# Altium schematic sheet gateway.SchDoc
size A3
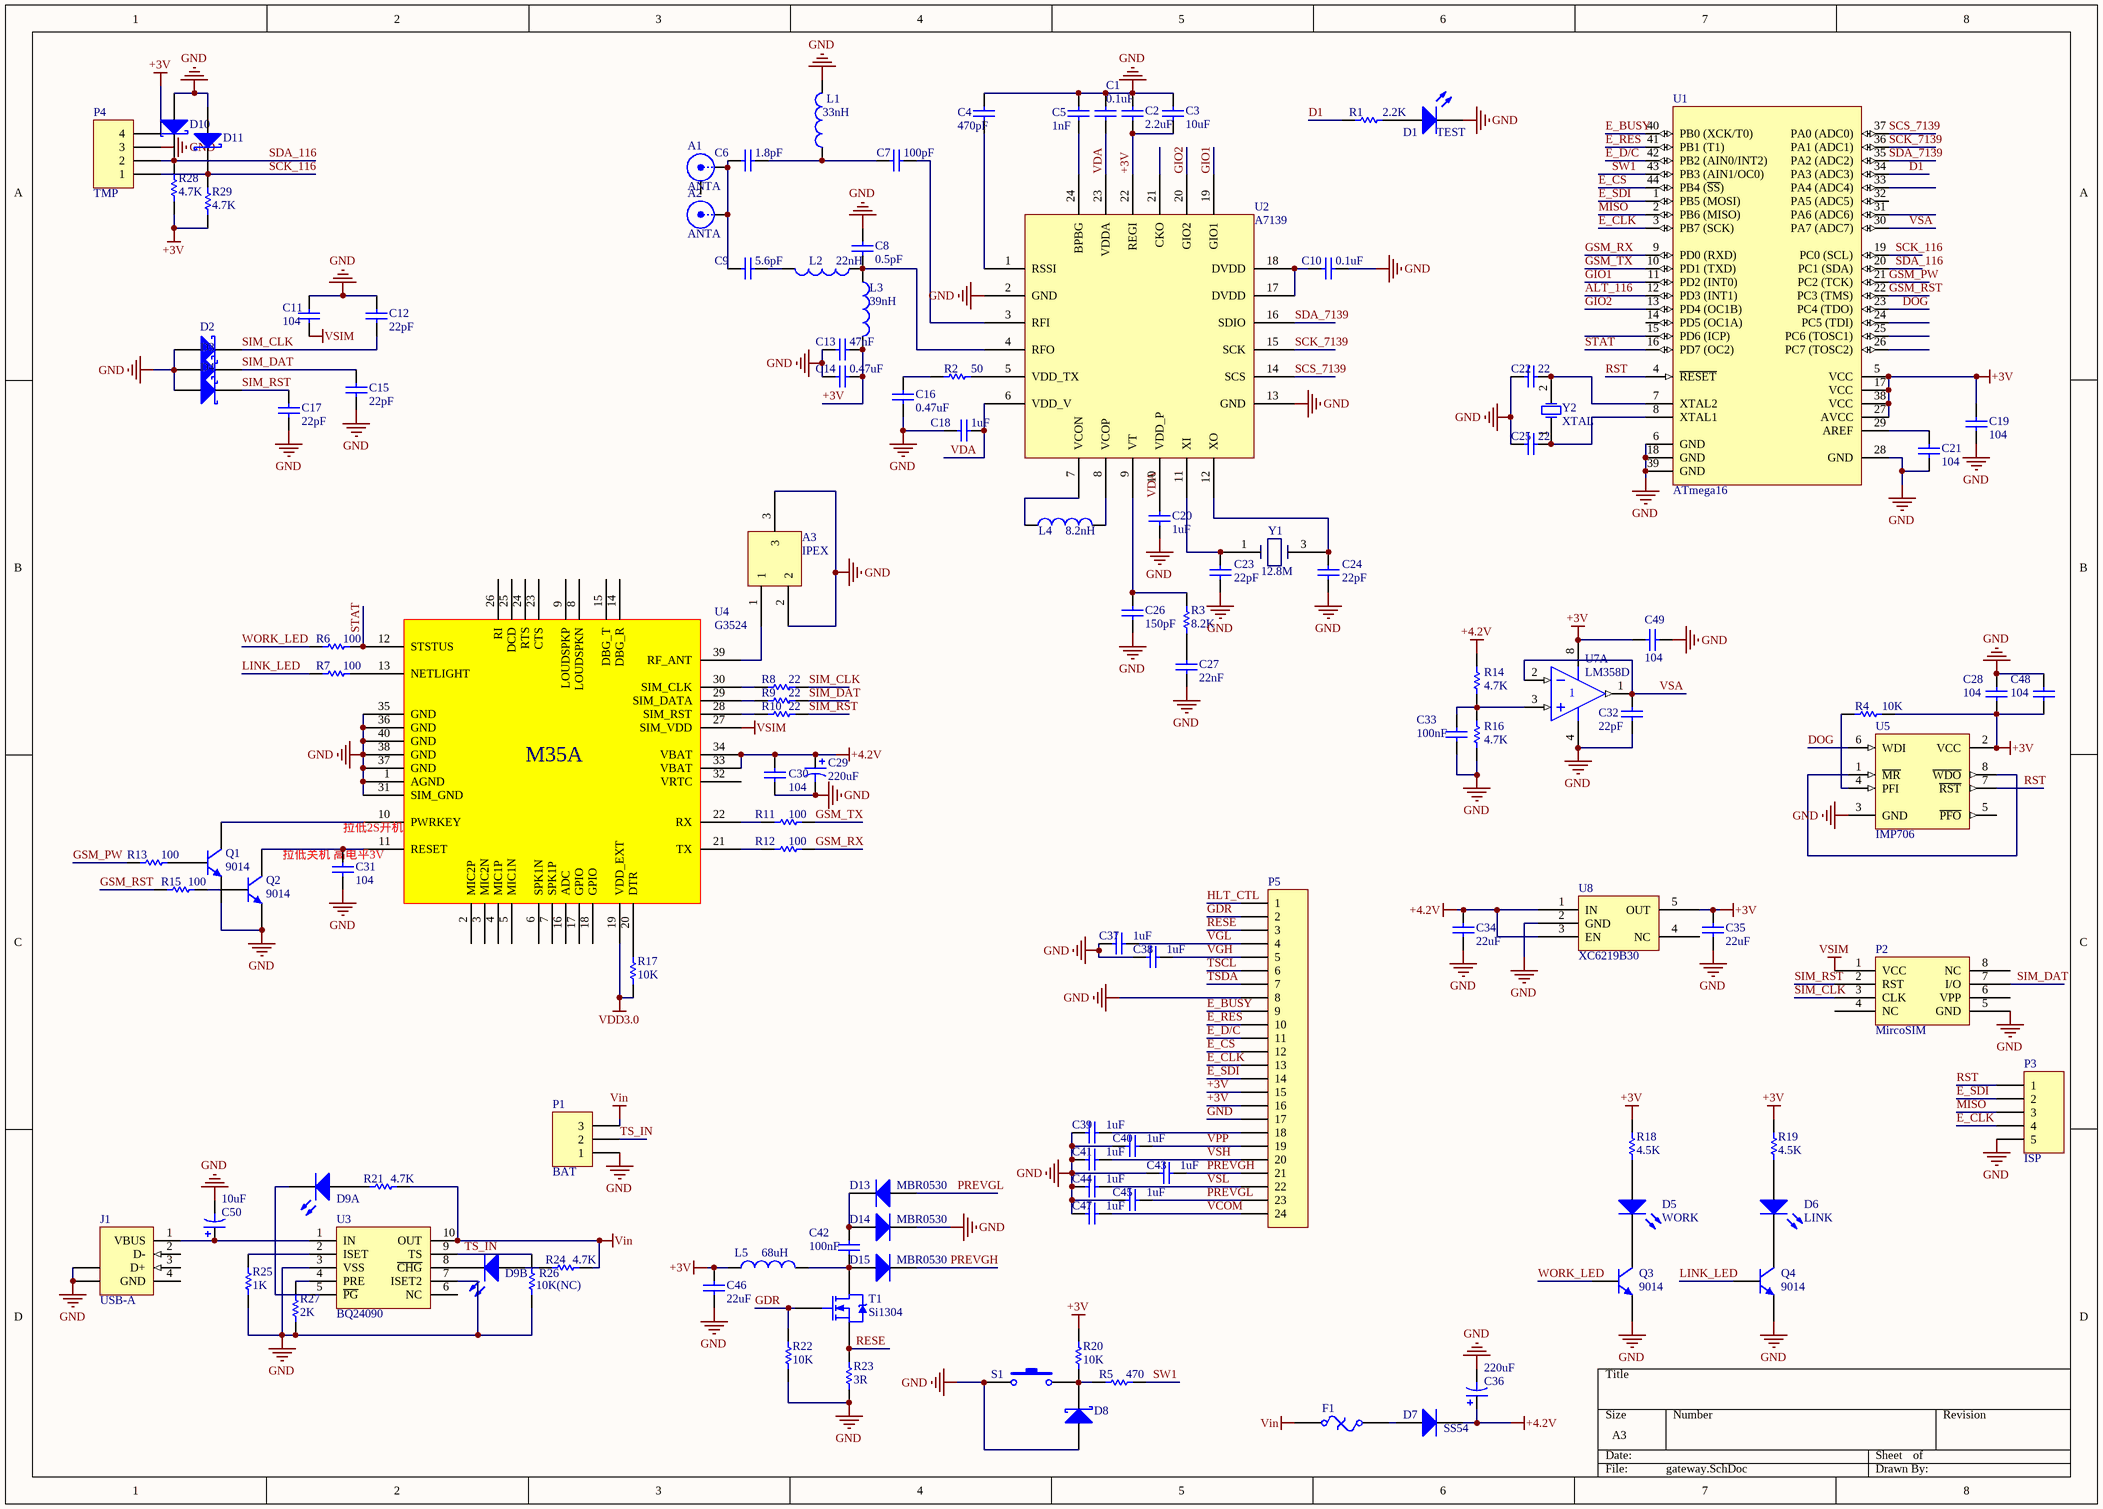
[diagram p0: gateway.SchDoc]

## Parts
A1  ANTA  [ANTA-433]
A2  ANTA  [IPEX]
A3  IPEX  [IPEX]
C1  value 0.1uF  [0402-A]  (hidden comment: Cap)
C2  value 2.2uF  [0603]  (hidden comment: Cap)
C3  value 10uF  [0603]  (hidden comment: Cap)
C4  value 470pF  [0402-A]  (hidden comment: Cap)
C5  value 1nF  [0402-A]  (hidden comment: Cap)
C6  value 1.8pF  [0402-A]  (hidden comment: Cap)
C7  value 100pF  [0402-A]  (hidden comment: Cap)
C8  value 0.5pF  [0402-A]  (hidden comment: Cap)
C9  value 5.6pF  [0402-A]  (hidden comment: Cap)
C10  value 0.1uF  [0402-A]  (hidden comment: Cap)
C11  value 104  [0603]  (hidden comment: Cap)
C12  value 22pF  [0603]  (hidden comment: Cap)
C13  value 47nF  [0402-A]  (hidden comment: Cap)
C14  value 0.47uF  [0402-A]  (hidden comment: Cap)
C15  value 22pF  [0603]  (hidden comment: Cap)
C16  value 0.47uF  [0402-A]  (hidden comment: Cap)
C17  value 22pF  [0603]  (hidden comment: Cap)
C18  value 1uF  [0402-A]  (hidden comment: Cap)
C19  value 104  [0603]  (hidden comment: Cap)
C20  value 1uF  [0402-A]  (hidden comment: Cap)
C21  value 104  [0603]  (hidden comment: Cap)
C22  value 22  [0603]  (hidden comment: Cap)
C23  value 22pF  [0402-A]  (hidden comment: Cap)
C24  value 22pF  [0402-A]  (hidden comment: Cap)
C25  value 22  [0603]  (hidden comment: Cap)
C26  value 150pF  [0402-A]  (hidden comment: Cap)
C27  value 22nF  [0402-A]  (hidden comment: Cap)
C28  value 104  [0603]  (hidden comment: Cap)
C29  value 220uF  [C7343]  (hidden comment: Cap Pol3)
C30  value 104  [0603]  (hidden comment: Cap)
C31  value 104  [0603]  (hidden comment: Cap)
C32  value 22pF  [0603]  (hidden comment: Cap)
C33  value 100nF  [0603]  (hidden comment: Cap)
C34  value 22uF  [3216[1206]]  (hidden comment: Cap)
C35  value 22uF  [3216[1206]]  (hidden comment: Cap)
C36  value 220uF  [C7343]  (hidden comment: Cap Pol3)
C37  value 1uF  [0603]  (hidden comment: Cap)
C38  value 1uF  [0603]  (hidden comment: Cap)
C39  value 1uF  [0603]  (hidden comment: Cap)
C40  value 1uF  [0603]  (hidden comment: Cap)
C41  value 1uF  [0603]  (hidden comment: Cap)
C42  value 100nF  [0603]  (hidden comment: Cap)
C43  value 1uF  [0603]  (hidden comment: Cap)
C44  value 1uF  [0603]  (hidden comment: Cap)
C45  value 1uF  [0603]  (hidden comment: Cap)
C46  value 22uF  [3216[1206]]  (hidden comment: Cap)
C47  value 1uF  [0603]  (hidden comment: Cap)
C48  value 104  [0603]  (hidden comment: Cap)
C49  value 104  [0603]  (hidden comment: Cap)
C50  value 10uF  [0805]  (hidden comment: Cap Pol3)
D1  TEST  [0603-LED]
D2  RL0603E012M100K  [0603]  (value not drawn)
D3  RL0603E012M100K  [0603]  (value not drawn)
D4  RL0603E012M100K  [0603]  (value not drawn)
D5  WORK  [0603-LED]
D6  LINK  [0603-LED]
D7  SS54  [SMA]
D8  RL0603E012M100K  [0603]  (value not drawn)
D9  LED  [0603-LED-DOUBLE]  (value not drawn)  (parts A,B of 2)
D10  RL0603E012M100K  [0603]  (value not drawn)
D11  RL0603E012M100K  [0603]  (value not drawn)
D13  MBR0530  [SOD-123]
D14  MBR0530  [SOD-123]
D15  MBR0530  [SOD-123]
F1  Fuse Thermal  [1812]  (value not drawn)
J1  USB-A  [MicroUSB]
L1  value 33nH  [0603]  (hidden comment: Inductor)
L2  value 22nH  [0603]  (hidden comment: Inductor)
L3  value 39nH  [0603]  (hidden comment: Inductor)
L4  value 8.2nH  [0402-A]  (hidden comment: Inductor)
L5  value 68uH  [14-1210]  (hidden comment: Inductor)
P1  BAT  [1.25-3P]
P2  MircoSIM  [Micro SIM]
P3  ISP  [HDR1X5]
P4  TMP  [1.25-4P]
P5  Header 24  [FPC-24]  (value not drawn)
Q1  value 9014  [SOT-23-NPN]  (hidden comment: NPN)
Q2  value 9014  [SOT-23-NPN]  (hidden comment: NPN)
Q3  value 9014  [SOT-23-NPN]  (hidden comment: NPN)
Q4  value 9014  [SOT-23-NPN]  (hidden comment: NPN)
R1  value 2.2K  [0603]  (hidden comment: Res1)
R2  value 50  [0402-A]  (hidden comment: Res1)
R3  value 8.2K  [0402-A]  (hidden comment: Res1)
R4  value 10K  [0603]  (hidden comment: Res1)
R5  value 470  [0603]  (hidden comment: Res1)
R6  value 100  [0603]  (hidden comment: Res1)
R7  value 100  [0603]  (hidden comment: Res1)
R8  value 22  [0603]  (hidden comment: Res1)
R9  value 22  [0603]  (hidden comment: Res1)
R10  value 22  [0603]  (hidden comment: Res1)
R11  value 100  [0603]  (hidden comment: Res1)
R12  value 100  [0603]  (hidden comment: Res1)
R13  value 100  [0603]  (hidden comment: Res1)
R14  value 4.7K  [0603]  (hidden comment: Res1)
R15  value 100  [0603]  (hidden comment: Res1)
R16  value 4.7K  [0603]  (hidden comment: Res1)
R17  value 10K  [0603]  (hidden comment: Res1)
R18  value 4.5K  [0603]  (hidden comment: Res1)
R19  value 4.5K  [0603]  (hidden comment: Res1)
R20  value 10K  [0603]  (hidden comment: Res1)
R21  value 4.7K  [0603]  (hidden comment: Res1)
R22  value 10K  [0603]  (hidden comment: Res1)
R23  value 3R  [0603]  (hidden comment: Res1)
R24  value 4.7K  [0603]  (hidden comment: Res1)
R25  value 1K  [0603]  (hidden comment: Res1)
R26  value 10K(NC)  [0603]  (hidden comment: Res1)
R27  value 2K  [0603]  (hidden comment: Res1)
R28  value 4.7K  [0603]  (hidden comment: Res1)
R29  value 4.7K  [0603]  (hidden comment: Res1)
S1  SW-PB  [SW1]  (value not drawn)
T1  Si1304  [SOT-23-NMOS]
U1  ATmega16  [44A_M]
U2  A7139  [QFN24N]
U3  BQ24090  [MSOP-PowerPAD-10]
U4  G3524  [G3524]
U5  IMP706  [SOIC8]
U7  LM358D  [SOIC8]  (part A of 2)
U8  XC6219B30  [SOT23-5N]
Y1  12.8M  [XT3225]
Y2  XTAL  [XT5032]

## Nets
+3V: C2.1 C3.1 C13.2 C14.2 C19.1 C28.2 C35.1 C46.1 C48.2 C49.1 L3.2 L5.1 P4.4 P5.15 P5.16 R4.2 R18.1 R19.1 R20.1 R28.2 R29.2 U1.5(VCC) U1.17(VCC) U1.27(AVCC) U1.38(VCC) U2.22(REGI) U5.2(VCC) U7.8(V+) U8.5(OUT)
+4.2V: C29.1 C30.2 C34.1 C36.1 D7.2(K) R14.2 U4.33(VBAT) U4.34(VBAT) U8.1(IN) U8.3(EN)
GND: A2.2(Y) A3.2 A3.3 C1.2 C2.2 C3.2 C4.2 C5.2 C8.2 C10.2 C11.1 C12.1 C13.1 C14.1 C15.2 C16.1 C17.2 C18.2 C19.2 C20.1 C21.2 C22.2 C23.1 C24.1 C25.2 C26.1 C27.2 C28.1 C29.2 C30.1 C31.2 C32.1 C33.2 C34.2 C35.2 C36.2 C37.1 C38.1 C39.1 C40.1 C41.1 C43.1 C44.1 C45.1 C46.2 C47.1 C48.1 C49.2 C50.2 D1.2(K) D2.2(A) D3.2(A) D4.2(A) D8.2(A) D10.2(A) D11.2(A) D14.2(K) J1.5(SHLD) J1.6(SHLD) L1.2 P1.1 P2.5(GND) P3.5 P4.3 P5.8 P5.17 Q1.1(E) Q2.1(E) Q3.1(E) Q4.1(E) R16.1 R22.2 R23.2 R25.1 R26.1 R27.1 S1.1 U1.6(GND) U1.18(GND) U1.28(GND) U1.39(GND) U2.2(GND) U2.13(GND) U2.25(GND) U3.3(VSS) U3.7(ISET2) U3.11 U4.1(AGND) U4.31(SIM_GND) U4.35(GND) U4.36(GND) U4.37(GND) U4.38(GND) U4.40(GND) U5.3(GND) U7.4(V-) U8.2(GND)
VDD3.0: R17.2 U4.19(VDD_EXT)
Vin: F1.1 P1.3 R21.2 R24.2 U3.10(OUT)
VSIM: C11.2 P2.1(VCC) U4.27(SIM_VDD)
ALT_116: U1.12(PD3_(INT1))
D1: R1.1 U1.34(PA3_(ADC3))
DOG: U1.23(PC4_(TDO)) U5.6(WDI)
E_BUSY: P5.9 U1.40(PB0_(XCK/T0))
E_CLK: P3.4 P5.13 U1.3(PB7_(SCK))
E_CS: P5.12 U1.44(PB4_(~{SS}))
E_D/C: P5.11 U1.42(PB2_(AIN0/INT2))
E_RES: P5.10 U1.41(PB1_(T1))
E_SDI: P3.2 P5.14 U1.1(PB5_(MOSI))
GDR: P5.2 R22.1 T1.1(G)
GIO1: U1.11(PD2_(INT0)) U2.19(GIO1)
GIO2: U1.13(PD4_(OC1B)) U2.20(GIO2)
GSM_PW: R13.2 U1.21(PC2_(TCK))
GSM_RST: R15.2 U1.22(PC3_(TMS))
GSM_RX: R12.2 U1.9(PD0_(RXD))
GSM_TX: R11.2 U1.10(PD1_(TXD))
HLT_CTL: P5.1
LINK_LED: Q4.2(B) R7.2
MISO: P3.3 U1.2(PB6_(MISO))
PREVGH: C43.2 D15.2(K) P5.21
PREVGL: C45.2 D13.1(A) P5.23
RESE: P5.3 R23.1 T1.3(S)
RST: P3.1 U1.4(~{RESET}) U5.7(~{RST})
SCK_116: D11.1(K) P4.1 R29.1 U1.19(PC0_(SCL))
SCK_7139: U1.36(PA1_(ADC1)) U2.15(SCK)
SCS_7139: U1.37(PA0_(ADC0)) U2.14(SCS)
SDA_116: D10.1(K) P4.2 R28.1 U1.20(PC1_(SDA))
SDA_7139: U1.35(PA2_(ADC2)) U2.16(SDIO)
SIM_CLK: C12.2 D2.1(K) P2.3(CLK) R8.1
SIM_DAT: C15.1 D3.1(K) P2.7(I/O) R9.1
SIM_RST: C17.1 D4.1(K) P2.2(RST) R10.1
STAT: R6.1 U1.16(PD7_(OC2)) U4.12(STSTUS)
SW1: R5.2 U1.43(PB3_(AIN1/OC0))
TS_IN: P1.2 R26.2 U3.9(TS)
TSCL: P5.6
TSDA: P5.7
VCOM: C47.2 P5.24
VDA: C1.1 C18.1 C20.2 U2.6(VDD_V) U2.10(VDD_P) U2.23(VDDA)
VGH: C38.2 P5.5
VGL: C37.2 P5.4
VPP: C40.2 P5.19
VSA: C32.2 U1.30(PA7_(ADC7)) U7.1(OUT) U7.2(IN-)
VSH: C41.2 P5.20
VSL: C44.2 P5.22
WORK_LED: Q3.2(B) R6.2
NetA1_1: A1.1(X) A2.1(X) C6.2 C9.2
NetA3_1: A3.1 U4.39(RF_ANT)
NetC4_1: C4.1 U2.1(RSSI)
NetC5_1: C5.1 U2.24(BPBG)
NetC6_1: C6.1 C7.2 L1.1
NetC7_1: C7.1 U2.3(RFI)
NetC8_1: C8.1 L2.1 L3.1 U2.4(RFO)
NetC9_1: C9.1 L2.2
NetC10_1: C10.1 U2.17(DVDD) U2.18(DVDD)
NetC16_2: C16.2 R2.2
NetC21_1: C21.1 U1.29(AREF)
NetC22_1: C22.1 U1.7(XTAL2) Y2.2(OSC2)
NetC23_2: C23.2 U2.11(XI) Y1.1
NetC24_2: C24.2 U2.12(XO) Y1.3
NetC25_1: C25.1 U1.8(XTAL1) Y2.1(OSC1)
NetC26_2: C26.2 R3.2 U2.9(VT)
NetC27_1: C27.1 R3.1
NetC31_1: C31.1 Q2.3(C) U4.11(RESET)
NetC33_1: C33.1 R14.1 R16.2 U7.3(IN+)
NetC39_2: C39.2 P5.18
NetC42_1: C42.1 D15.1(A) L5.2 T1.2(D)
NetC42_2: C42.2 D13.2(K) D14.1(A)
NetC50_1: C50.1 J1.1(VBUS) U3.1(IN)
NetD1_1: D1.1(A) R1.2
NetD5_1: D5.1(A) R18.2
NetD5_2: D5.2(K) Q3.3(C)
NetD6_1: D6.1(A) R19.2
NetD6_2: D6.2(K) Q4.3(C)
NetD7_1: D7.1(A) F1.2
NetD8_1: D8.1(K) R5.1 R20.2 S1.2
NetD9_1: D9.1(A) R21.1
NetD9_2: D9.2(K) U3.5(~{PG})
NetD9_3: D9.3 R24.1
NetD9_4: D9.4 U3.8(~{CHG})
NetL4_1: L4.1 U2.7(VCON)
NetL4_2: L4.2 U2.8(VCOP)
NetQ1_2: Q1.2(B) R13.1
NetQ1_3: Q1.3(C) U4.10(PWRKEY)
NetQ2_2: Q2.2(B) R15.1
NetR2_1: R2.1 U2.5(VDD_TX)
NetR4_1: R4.1 U5.4(PFI)
NetR7_1: R7.1 U4.13(NETLIGHT)
NetR8_2: R8.2 U4.30(SIM_CLK)
NetR9_2: R9.2 U4.29(SIM_DATA)
NetR10_2: R10.2 U4.28(SIM_RST)
NetR11_1: R11.1 U4.22(RX)
NetR12_1: R12.1 U4.21(TX)
NetR17_1: R17.1 U4.20(DTR)
NetR25_2: R25.2 U3.2(ISET)
NetR27_2: R27.2 U3.4(PRE)
NetU5_1: U5.1(~{MR}) U5.8(~{WDO})

Not connected (* = marked no-connect by the designer): A1 2(Y); J1 2(D-) 3(D+) 4(GND); P2 4(NC) 6(VPP) 8(NC); U1 14(PD5_(OC1A)) 15(PD6_(ICP)) 24(PC5_(TDI)) 25(PC6_(TOSC1)) 26(PC7_(TOSC2)) 31(PA6_(ADC6)) 32(PA5_(ADC5)) 33(PA4_(ADC4)); U2 21(CKO); U3 6(NC); U4 2(MIC2P) 3(MIC2N) 4(MIC1P) 5(MIC1N) 6(SPK1N) 7(SPK1P) 8(LOUDSPKN) 9(LOUDSPKP) 14(DBG_R) 15(DBG_T) 16(ADC) 17(GPIO) 18(GPIO) 23(CTS) 24(RTS) 25(DCD) 26(RI) 32(VRTC); U5 5(~{PFO}); U8 4(NC)

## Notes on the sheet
- (near C31) 拉低关机 高电平3V
- 拉低2S开机

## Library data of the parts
A1 A2 = SMB: SMB Straight Connector
C1-C28 C30-C35 C37-C49 = Cap: Capacitor
C29 C36 C50 = Cap Pol3: Polarized Capacitor (Surface Mount)
D1 D5 D6 = LED2: Typical RED, GREEN, YELLOW, AMBER GaAs LED; Value: GRN
D2-D4 D8 D10 D11 = Diode 18TQ045: Schottky Rectifier; Note: Terminal 2 is the TAB and is electrically connected to the cathode; Value: SMBJ45CA
D7 = Diode 1N5408: 3 Amp Medium Power Silicon Rectifier Diode
D9 = LED-DOUBLE
D13-D15 = Diode 1N5408: 3 Amp Medium Power Silicon Rectifier Diode; Value: SS54
F1 = Fuse Thermal: Thermal Fuse
J1 = 440314-1: USB 1.1, Right Angle, Thru-Hole, Series A, Reverse Type, Receptacle, 4 Position, Black; ContactMaterial: Copper Alloy; ContactPlating: Gold (30); TerminationLength: 2.22mm [0.088in.]; PCB_Layout: Complies with manufacturer's recommendation.; DrillSize: Corresponds to nominal value.; PanelGround: Without
L1-L5 = Inductor: Code_IEC: 1005
P1 = Header 3: Header, 3-Pin
P3 = Header 5: Header, 5-Pin
P4 = Header 4: Header, 4-Pin
P5 = Header 24: Header, 24-Pin
Q1-Q4 = 2N5551: NPN General Purpose Amplifier
R1-R29 = Res1: Resistor
S1 = SW-PB: Switch
T1 = IRF644S: HEXFET N-Channel Power MOSFET
U1 = ATmega16-16AI: 8-Bit AVR Microcontroller with 16K Bytes of In-System Programmable Flash Memory
U5 = MAX706RCSA: +3V Voltage Monitoring, Low-Cost, 礟 Supervisory Circuit
U7 = LM358D: Dual Low-Power Operational Amplifier
U8 = LP5907: Value: LP5907
Y1 = 3225-wy
Y2 = XTAL: Crystal Oscillator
